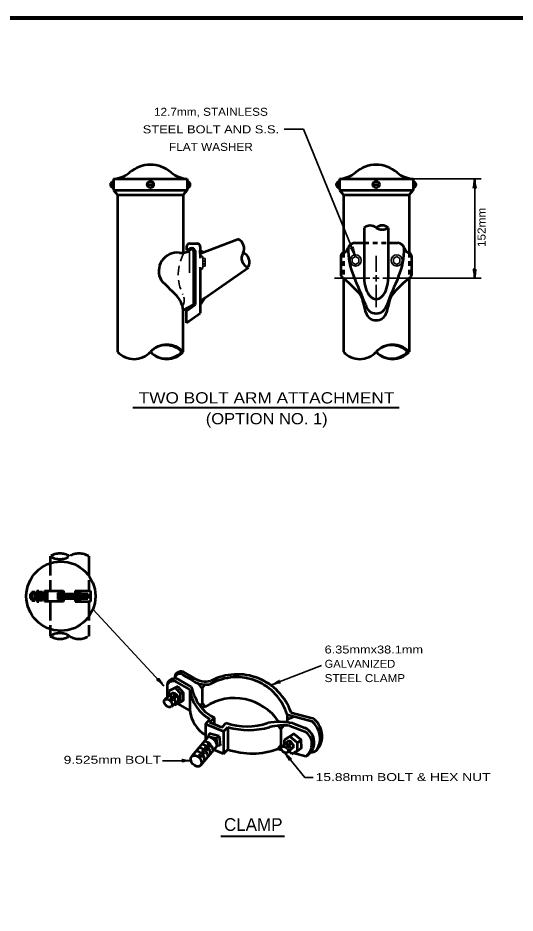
# Model space of a CAD drawing. Extents: x 6460 to 7173, y 270 to 723.
# Drawn here: x 6645 to 6801.5, y 436 to 717.8 of the extents above; entities that cross this region are included whole.
import ezdxf
from ezdxf.enums import TextEntityAlignment as Align

# ---------------------------------------------------------------- set-up
doc = ezdxf.new("R2010")
doc.units = 0
for name, pattern in [('LONG_DASHED', [7.5, 6, -1.5]), ('MEDIUM_DASHED', [4.5, 3, -1.5]), ('SHORT_DASHED', [2.7, 1.5, -1.2])]:
    doc.linetypes.add(name, pattern=pattern)
doc.layers.add('1', color=7, linetype='Continuous', lineweight=35)

msp = doc.modelspace()

# ---------------------------------------------------------------- linework, layer by layer
at = {"layer": '1'}
for p, q in [((6728.799, 682.801), (6734.872, 682.801)), ((6751.122, 642.92), (6734.872, 682.801)), ((6769.322, 667.1), (6790.742, 667.1)), ((6788.742, 667.1), (6788.742, 635.86)), ((6698.982, 637.52), (6698.982, 644.38)), ((6700.122, 627.44), (6700.122, 644.06)), ((6751.242, 642.68), (6750.222, 642.06)), ((6751.242, 642.68), (6752.242, 642.06)), ((6757.742, 642.92), (6757.742, 637.86)), ((6764.222, 642.68), (6763.222, 642.06)), ((6764.222, 642.68), (6765.222, 642.06)), ((6703.122, 639.08), (6703.122, 642.44)), ((6703.882, 641.26), (6703.142, 641.26)), ((6703.882, 640.4), (6703.142, 640.4)), ((6750.222, 642.06), (6750.222, 640.8)), ((6752.242, 642.06), (6752.242, 640.8)), ((6763.222, 642.06), (6763.222, 640.8)), ((6765.222, 642.06), (6765.222, 640.8)), ((6703.882, 639.66), (6703.142, 639.66)), ((6744.642, 635.86), (6755.742, 635.86)), ((6756.702, 635.86), (6758.722, 635.86)), ((6757.742, 636.84), (6757.742, 634.84)), ((6759.782, 635.86), (6790.742, 635.86)), ((6757.742, 633.82), (6757.742, 626.78)), ((6668.533, 531.678), (6690.869, 507.577)), ((6724.751, 507.828), (6740.562, 513.979)), ((6699.435, 483.978), (6690.434, 483.978))]:
    msp.add_line(p, q, dxfattribs=at)
at = {"layer": '1', "lineweight": 53}
for p, q in [((6674.082, 665.34), (6674.822, 665.34)), ((6675.082, 667.1), (6698.262, 667.1)), ((6675.082, 667.1), (6675.082, 663.58)), ((6685.902, 665.34), (6687.422, 665.34)), ((6698.262, 667.1), (6698.262, 663.58)), ((6698.522, 665.34), (6699.222, 665.34)), ((6745.142, 665.34), (6745.902, 665.34)), ((6746.142, 667.1), (6769.322, 667.1)), ((6746.142, 667.1), (6746.142, 663.58)), ((6756.982, 665.34), (6758.482, 665.34)), ((6769.322, 667.1), (6769.322, 663.58)), ((6769.582, 665.34), (6770.282, 665.34)), ((6675.082, 663.58), (6698.262, 663.58)), ((6675.082, 663.58), (6676.342, 662.06)), ((6698.262, 663.58), (6697.002, 662.06)), ((6746.142, 663.58), (6769.322, 663.58)), ((6746.142, 663.58), (6747.402, 662.06)), ((6769.322, 663.58), (6768.062, 662.06)), ((6676.342, 662.06), (6676.342, 612.68)), ((6676.342, 662.06), (6697.002, 662.06)), ((6697.002, 662.06), (6697.002, 643.92)), ((6747.402, 662.06), (6768.062, 662.06)), ((6747.402, 662.06), (6747.402, 643.92)), ((6768.062, 662.06), (6768.062, 643.92)), ((6753.962, 651.74), (6753.962, 635.86)), ((6761.522, 651.74), (6761.522, 635.86)), ((6702.362, 643.64), (6714.222, 648.18)), ((6698.022, 645.76), (6698.022, 644.72)), ((6699.022, 646.76), (6701.362, 646.76)), ((6702.362, 645.76), (6702.362, 645.24)), ((6750.882, 646.98), (6753.962, 646.98)), ((6761.522, 646.98), (6764.582, 646.98)), ((6698.022, 644.72), (6698.522, 644.72)), ((6700.902, 627.58), (6700.902, 643.76)), ((6702.362, 645.24), (6702.362, 642.2)), ((6746.642, 642.92), (6746.642, 636.86)), ((6768.822, 642.92), (6768.822, 636.86)), ((6702.362, 639.32), (6702.362, 629.74)), ((6702.362, 628.68), (6717.502, 639.28)), ((6747.402, 635.86), (6747.402, 612.68)), ((6768.062, 635.86), (6768.062, 612.68)), ((6702.362, 629.74), (6702.362, 624.9)), ((6697.002, 625.78), (6700.122, 627.44)), ((6697.002, 612.68), (6697.002, 625.78)), ((6698.022, 625.56), (6700.902, 627.58)), ((6698.022, 621.86), (6698.022, 625.56)), ((6698.022, 621.86), (6702.362, 624.9)), ((6648.782, 536.53), (6648.782, 535.01)), ((6648.782, 536.53), (6653.322, 536.53)), ((6649.082, 535.91), (6649.082, 535.61)), ((6649.382, 537.13), (6649.382, 534.41)), ((6649.382, 537.13), (6650.302, 537.13)), ((6650.302, 537.13), (6650.302, 534.41)), ((6650.902, 537.43), (6650.902, 534.11)), ((6650.902, 537.43), (6651.502, 537.43)), ((6651.502, 537.43), (6651.502, 534.11)), ((6652.122, 537.13), (6652.122, 534.41)), ((6652.122, 537.13), (6652.722, 537.13)), ((6652.722, 537.13), (6652.722, 534.41)), ((6653.322, 537.43), (6653.322, 534.11)), ((6653.322, 537.43), (6659.362, 537.43)), ((6654.222, 537.43), (6654.222, 534.11)), ((6657.562, 536.83), (6658.762, 536.83)), ((6657.562, 536.83), (6657.562, 534.71)), ((6657.862, 536.23), (6658.762, 536.23)), ((6658.762, 537.43), (6658.762, 534.11)), ((6659.362, 537.43), (6659.362, 534.11)), ((6659.822, 536.07), (6659.822, 535.47)), ((6660.282, 536.53), (6660.282, 535.01)), ((6660.722, 536.07), (6660.722, 535.47)), ((6661.182, 536.53), (6661.182, 535.01)), ((6661.642, 536.07), (6661.642, 535.47)), ((6662.102, 536.53), (6662.102, 535.01)), ((6662.542, 536.07), (6662.542, 535.47)), ((6663.002, 537.43), (6663.002, 534.11)), ((6663.002, 537.43), (6667.842, 537.43)), ((6663.602, 537.43), (6663.602, 534.11)), ((6664.822, 536.83), (6663.622, 536.83)), ((6664.522, 536.23), (6663.622, 536.23)), ((6664.822, 535.61), (6664.522, 535.31)), ((6664.822, 536.83), (6664.822, 534.71)), ((6665.342, 536.07), (6665.342, 535.47)), ((6665.882, 536.53), (6665.882, 535.01)), ((6666.402, 536.07), (6666.402, 535.47)), ((6666.922, 536.53), (6666.922, 535.01)), ((6667.842, 537.43), (6667.842, 534.11)), ((6648.782, 535.01), (6653.322, 535.01)), ((6649.382, 534.41), (6650.302, 534.41)), ((6650.902, 534.11), (6651.502, 534.11)), ((6652.722, 534.41), (6652.122, 534.41)), ((6659.362, 534.11), (6653.322, 534.11)), ((6657.562, 534.71), (6658.762, 534.71)), ((6657.862, 535.31), (6658.762, 535.31)), ((6663.002, 534.11), (6667.842, 534.11)), ((6664.522, 535.31), (6663.622, 535.31)), ((6664.822, 534.71), (6663.622, 534.71)), ((6664.522, 535.31), (6664.822, 535.01)), ((6700.179, 510.074), (6696.959, 511.914)), ((6700.179, 509.114), (6696.959, 510.934)), ((6691.919, 507.834), (6691.919, 503.814)), ((6695.259, 507.354), (6692.579, 505.934)), ((6699.039, 506.354), (6695.019, 508.654)), ((6699.539, 507.234), (6695.519, 509.514)), ((6702.979, 506.694), (6701.699, 508.334)), ((6702.979, 506.694), (6703.939, 507.934)), ((6693.479, 505.234), (6691.219, 503.194)), ((6692.579, 504.434), (6692.579, 505.934)), ((6694.499, 506.954), (6696.119, 505.154)), ((6699.039, 506.354), (6699.039, 499.794)), ((6695.499, 502.974), (6693.259, 500.954)), ((6694.099, 501.734), (6694.299, 501.494)), ((6699.039, 499.794), (6695.239, 501.954)), ((6702.979, 502.154), (6703.919, 500.974)), ((6702.499, 501.154), (6703.919, 500.974)), ((6730.919, 499.174), (6737.739, 497.354)), ((6704.059, 495.514), (6705.419, 497.014)), ((6705.379, 496.054), (6706.739, 497.554)), ((6709.099, 494.474), (6705.379, 496.054)), ((6706.739, 497.554), (6706.739, 495.474)), ((6729.699, 498.474), (6737.479, 496.374)), ((6729.699, 498.474), (6729.699, 496.054)), ((6729.819, 497.014), (6731.899, 497.874)), ((6709.639, 493.154), (6704.059, 495.514)), ((6704.059, 495.514), (6704.059, 490.534)), ((6709.099, 494.474), (6710.519, 495.894)), ((6709.639, 493.154), (6711.059, 494.574)), ((6709.639, 493.154), (6709.639, 486.094)), ((6711.059, 494.574), (6711.059, 487.514)), ((6727.739, 493.954), (6726.899, 495.014)), ((6727.739, 493.954), (6728.619, 495.094)), ((6727.739, 493.954), (6727.739, 488.914)), ((6730.579, 494.994), (6735.299, 493.194)), ((6731.459, 495.774), (6735.239, 494.334)), ((6704.899, 491.534), (6699.719, 485.354)), ((6705.139, 492.514), (6704.899, 491.534)), ((6707.399, 490.914), (6704.899, 491.534)), ((6708.319, 491.734), (6705.139, 492.514)), ((6708.319, 491.734), (6707.399, 490.914)), ((6707.399, 490.914), (6707.659, 488.614)), ((6708.319, 491.734), (6708.659, 488.734)), ((6728.919, 489.174), (6728.879, 490.534)), ((6732.919, 489.654), (6730.599, 491.594)), ((6707.659, 488.614), (6702.459, 482.434)), ((6708.659, 488.734), (6707.659, 488.614)), ((6709.639, 486.094), (6711.059, 487.514)), ((6727.739, 488.914), (6726.799, 487.714)), ((6726.799, 487.714), (6727.899, 487.414)), ((6727.739, 488.914), (6728.119, 488.414)), ((6730.099, 490.274), (6727.879, 488.214)), ((6731.819, 488.434), (6729.979, 486.714)), ((6709.639, 486.094), (6706.619, 487.374)), ((6731.219, 486.174), (6730.259, 486.974)), ((6731.679, 486.414), (6735.559, 485.374))]:
    msp.add_line(p, q, dxfattribs=at)
at = {"layer": '1', "linetype": 'SHORT_DASHED', "lineweight": 53}
for p, q in [((6753.962, 646.98), (6761.522, 646.98)), ((6747.402, 643.92), (6747.402, 635.86)), ((6768.062, 643.92), (6768.062, 635.86))]:
    msp.add_line(p, q, dxfattribs=at)
at = {"layer": '1', "lineweight": 40}
for p, q in [((6681.102, 595.14), (6764.982, 595.14)), ((6708.814, 460.253), (6728.892, 460.253))]:
    msp.add_line(p, q, dxfattribs=at)
at = {"layer": '1', "linetype": 'LONG_DASHED', "lineweight": 53}
for p, q in [((6655.142, 548.31), (6655.142, 537.43)), ((6667.242, 548.31), (6667.242, 537.43)), ((6655.142, 534.11), (6655.142, 523.21)), ((6667.242, 534.11), (6667.242, 523.21))]:
    msp.add_line(p, q, dxfattribs=at)
at = {"layer": '1', "lineweight": 158}
msp.add_lwpolyline([(7167.871, 717.799), (6508.121, 717.715), (6508.204, 279.382)], dxfattribs=at)
at = {"layer": '1', "lineweight": 53}
for points in [[(6703.462, 644.06), (6702.362, 643.64), (6702.362, 644.68)], [(6702.382, 627.44), (6702.382, 628.7), (6704.042, 629.88)], [(6657.562, 536.53), (6657.862, 536.23), (6657.562, 535.91)], [(6657.562, 535.61), (6657.862, 535.31), (6657.562, 535.01)], [(6659.362, 536.53), (6660.282, 536.53), (6661.182, 536.53), (6662.102, 536.53), (6663.002, 536.53)], [(6664.822, 536.53), (6664.522, 536.23), (6664.822, 535.91)], [(6664.822, 536.53), (6665.882, 536.53), (6666.922, 536.53)], [(6659.362, 535.01), (6661.182, 535.01), (6663.002, 535.01)], [(6664.822, 535.01), (6665.882, 535.01), (6666.922, 535.01)], [(6695.259, 507.354), (6696.939, 505.494), (6696.939, 502.974), (6696.119, 502.394), (6694.299, 501.494)], [(6696.119, 502.394), (6696.119, 505.154), (6696.939, 505.494)], [(6702.979, 506.694), (6702.979, 502.154), (6702.339, 501.354)], [(6731.219, 486.174), (6732.999, 487.134), (6734.239, 487.994), (6734.159, 490.514), (6731.839, 492.454), (6728.879, 490.534)], [(6732.999, 487.134), (6732.919, 489.654), (6734.159, 490.514)]]:
    msp.add_lwpolyline(points, dxfattribs=at)
at = {"layer": '1'}
for points in [[(6703.882, 639.66), (6703.882, 642.02), (6703.142, 642.02)], [(6752.242, 640.8), (6751.242, 640.16), (6750.222, 640.8)], [(6765.222, 640.8), (6764.222, 640.16), (6763.222, 640.8)], [(6728.898, 486.568), (6735.292, 478.706), (6737.927, 478.706)]]:
    msp.add_lwpolyline(points, dxfattribs=at)
at = {"layer": '1', "lineweight": 53}
for centre, radius in [((6686.667, 665.34), 1.008), ((6757.731, 665.34), 1.008), ((6658.497, 535.774), 10.886)]:
    msp.add_circle(centre, radius, dxfattribs=at)
at = {"layer": '1'}
for centre in [(6751.248, 641.454), (6764.227, 641.446)]:
    msp.add_circle(centre, 1.764, dxfattribs=at)
at = {"layer": '1', "lineweight": 53}
for centre, radius, start, end in [((6686.673, 661.531), 10.025, 49.18722, 130.81278), ((6757.737, 661.531), 10.025, 49.18722, 130.81278), ((6674.151, 676.735), 9.678, 275.5142, 308.08862), ((6699.195, 676.735), 9.678, 231.91138, 264.4858), ((6745.215, 676.735), 9.678, 275.5142, 308.08862), ((6770.259, 676.735), 9.678, 231.91138, 264.4858), ((6675.087, 665.312), 1.008, 90.3199, 269.6801), ((6698.218, 665.312), 1.008, 272.67956, 87.32044), ((6746.151, 665.312), 1.008, 90.3199, 269.6801), ((6769.282, 665.312), 1.008, 272.67956, 87.32044), ((6755.847, 649.542), 2.891, 49.17959, 130.82041), ((6759.627, 649.649), 2.812, 47.76241, 132.23758), ((6759.627, 654.476), 3.333, 235.45601, 304.54399), ((6712.915, 645.177), 3.282, 333.96531, 66.42353), ((6699.021, 645.755), 1.008, 90, 180), ((6701.356, 645.755), 1.008, 0, 90), ((6746.746, 645.959), 2.235, 294.0674, 346.32146), ((6771.756, 645.164), 22.84, 179.33091, 202.67617), ((6751.02, 644.782), 2.2, 93.41837, 162.8601), ((6764.455, 644.782), 2.2, 17.1399, 86.58162), ((6743.719, 645.164), 22.84, 337.32383, 0.66909), ((6768.729, 645.959), 2.235, 193.67854, 245.9326), ((6695.102, 638.114), 5.805, 83.22236, 210.1126), ((6696.073, 652.427), 8.553, 268.07998, 289.90391), ((6699.611, 643.99), 1.312, 350.09958, 146.42495), ((6703.777, 645.898), 1.866, 221.01419, 260.32206), ((6718.267, 642.095), 2.91, 145.65086, 254.73799), ((6714.611, 640.856), 3.282, 333.96531, 66.42353), ((6747.714, 642.853), 1.067, 93.07015, 176.92984), ((6767.76, 642.853), 1.067, 3.07016, 86.92985), ((6747.714, 636.919), 1.067, 183.07016, 253.15341), ((6767.76, 636.919), 1.067, 286.84659, 356.92984), ((7805.326, 1750.591), 1577.297, 225.00367, 225.22952), ((6720.251, 603.149), 42.543, 42.29957, 50.33685), ((6568.182, 554.45), 200.037, 21.39177, 24.17121), ((6951.517, 552.676), 204.618, 155.85991, 158.57712), ((6795.223, 603.149), 42.543, 129.66315, 138.49633), ((6748.598, 627.807), 5.052, 9.48157, 51.86654), ((6767.078, 627.474), 5.329, 133.87214, 169.50589), ((6688.926, 624.885), 8.128, 6.28285, 46.84726), ((6710.958, 623.346), 9.51, 136.62273, 154.46868), ((6675.522, 606.627), 81.104, 13.13509, 15.74771), ((6839.953, 606.627), 81.104, 163.98892, 166.86491), ((6757.737, 628.174), 3.386, 193.00171, 346.99829), ((6757.737, 625.968), 3.36, 195.72161, 344.27839), ((6691.839, 607.854), 7.063, 42.99091, 137.00909), ((6691.579, 607.981), 6.786, 43.44505, 136.28697), ((6762.903, 607.854), 7.063, 42.99091, 137.00909), ((6762.643, 607.981), 6.786, 43.44505, 136.28697), ((6681.507, 617.486), 7.063, 222.99091, 317.00909), ((6691.839, 617.486), 7.063, 222.99091, 317.00909), ((6691.6, 617.326), 6.779, 223.38031, 316.35171), ((6752.571, 617.486), 7.063, 222.99091, 317.00909), ((6762.903, 617.486), 7.063, 222.99091, 317.00909), ((6762.664, 617.326), 6.779, 223.38031, 316.35171), ((6696.262, 510.077), 1.967, 68.98454, 184.96528), ((6695.905, 509.73), 1.613, 48.79801, 173.73367), ((6704.074, 516.05), 7.131, 236.83956, 283.32479), ((6714.037, 493.271), 17.892, 19.29143, 117.70819), ((6713.827, 493.697), 16.566, 16.7434, 119.30902), ((6694.333, 507.361), 2.464, 61.16852, 169.07366), ((6693.826, 506.869), 2.14, 56.06469, 153.37669), ((6704.022, 514.783), 6.854, 235.84201, 284.32234), ((6693.62, 503.323), 1.909, 349.61263, 94.38617), ((6693.244, 502.994), 1.742, 20.88408, 69.09679), ((6711.687, 508.143), 12.777, 188.06983, 240.59731), ((6720.612, 512.954), 21.84, 195.21089, 204.37149), ((6692.648, 502.453), 1.909, 349.61263, 94.38617), ((6692.192, 502.067), 1.742, 20.88408, 69.09679), ((6711.867, 508.402), 12.008, 201.80286, 244.70416), ((6713.072, 486.783), 16.89, 33.86522, 122.8499), ((6709.752, 501.171), 10.803, 187.30417, 238.23787), ((6727.212, 474.447), 21.748, 78.72641, 99.48511), ((6733.153, 490.957), 6.939, 327.83586, 51.43283), ((6733.979, 491.748), 6.752, 318.38164, 56.15447), ((6717.076, 514.154), 19.396, 250.25742, 289.74258), ((6717.61, 516.375), 22.763, 253.27137, 286.72862), ((6728.644, 475.321), 19.77, 84.35687, 103.10294), ((6733.254, 489.771), 4.969, 297.71146, 66.56345), ((6732.821, 489.19), 4.701, 305.70046, 58.26699), ((6704.468, 488.36), 3.193, 4.65558, 82.27962), ((6701.658, 484.847), 3.193, 7.29827, 83.92311), ((6702.422, 485.916), 3.193, 4.74535, 82.35434), ((6703.108, 486.603), 1.531, 14.18506, 70.66849), ((6703.247, 486.924), 3.193, 4.32722, 81.54855), ((6703.902, 487.673), 1.531, 14.18506, 70.66849), ((6718.651, 509.525), 23.278, 250.96338, 290.4942), ((6728.592, 487.125), 2.406, 11.41742, 74.57891), ((6728.836, 487.435), 1.432, 21.50211, 64.13038), ((6729.458, 487.95), 2.406, 11.41742, 74.57891), ((6729.712, 488.237), 1.432, 21.50211, 64.13038), ((6700.651, 483.778), 3.193, 5.19441, 82.73082), ((6701.275, 484.465), 1.531, 14.18506, 70.66849), ((6702.252, 485.565), 1.531, 14.18506, 70.66849), ((6736.852, 490.31), 3.743, 273.11257, 305.52158)]:
    msp.add_arc(centre, radius, start, end, dxfattribs=at)
at = {"layer": '1', "linetype": 'MEDIUM_DASHED'}
for centre, radius, start, end in [((6709.666, 636.948), 14.228, 150.47291, 206.06704), ((6693.269, 628.929), 4.026, 330.81735, 26.04877)]:
    msp.add_arc(centre, radius, start, end, dxfattribs=at)
at = {"layer": '1'}
for centre, radius, start, end in [((6699.538, 644.172), 0.593, 349.37883, 158.91973), ((6702.406, 642.274), 0.738, 13.64106, 87.59419), ((6702.406, 639.246), 0.738, 272.40581, 346.35894)]:
    msp.add_arc(centre, radius, start, end, dxfattribs=at)
at = {"layer": '1', "linetype": 'LONG_DASHED', "lineweight": 53}
for centre, start, end in [((6658.162, 543.585), 57.42639, 122.57361), ((6658.162, 553.052), 237.42639, 302.57361), ((6664.21, 543.585), 57.42639, 122.57361), ((6658.162, 518.486), 57.42639, 122.57361), ((6658.162, 527.953), 237.42639, 302.57361), ((6664.21, 527.953), 237.42639, 302.57361)]:
    msp.add_arc(centre, 5.617, start, end, dxfattribs=at)
at = {"layer": '1', "lineweight": 40}
for centre, major_axis, ratio, start_param, end_param in [((6788.52, 665.973), (0.177, 1.77), 0.07063, 3.1407148, 5.41811), ((6789.012, 666.002), (-0.157, 1.8), 0.122415, 0.8963533, 3.1415927), ((6750.444, 643.832), (0.824, -1.608), 0.122415, 0.8963533, 3.1415927), ((6750.888, 644.045), (-0.503, 1.707), 0.07063, 6.2823074, 8.5597026), ((6788.455, 636.954), (0.157, -1.8), 0.122415, 0.8963533, 3.1415927), ((6788.947, 636.984), (-0.177, -1.77), 0.07063, 3.1407148, 5.41811), ((6689.925, 508.19), (1.328, -1.204), 0.122415, 0.8963533, 3.1415927), ((6690.263, 508.543), (1.065, -1.408), 0.07063, 3.1407148, 5.41811), ((6725.668, 508.481), (-1.608, -0.793), 0.122415, 0.8963533, 3.1415927), ((6725.668, 508.481), (-1.608, -0.793), 0.122415, 0.8963533, 3.1415927), ((6725.872, 508.037), (-1.701, -0.473), 0.07063, 3.1407148, 5.41811), ((6725.872, 508.037), (-1.701, -0.473), 0.07063, 3.1407148, 5.41811), ((6729.44, 485.565), (0.972, -1.474), 0.07063, 6.2823074, 8.5597026), ((6729.44, 485.565), (0.972, -1.474), 0.07063, 6.2823074, 8.5597026), ((6729.801, 485.896), (-1.248, 1.287), 0.122415, 0.8963533, 3.1415927), ((6729.801, 485.896), (-1.248, 1.287), 0.122415, 0.8963533, 3.1415927), ((6698.344, 483.702), (1.786, 0.156), 0.122415, 0.8963533, 3.1415927), ((6698.344, 483.702), (1.786, 0.156), 0.122415, 0.8963533, 3.1415927), ((6698.314, 484.189), (1.756, -0.176), 0.07063, 3.1407148, 5.41811), ((6698.314, 484.189), (1.756, -0.176), 0.07063, 3.1407148, 5.41811)]:
    msp.add_ellipse(centre, major_axis=major_axis, ratio=ratio, start_param=start_param, end_param=end_param, dxfattribs=at)
at = {"layer": '1', "lineweight": 53}
msp.add_ellipse((6757.737, 635.854), major_axis=(0, 6.553), ratio=0.576878, start_param=1.5707963, end_param=4.712389, dxfattribs=at)
for centre, major_axis, ratio in [((6692.239, 502.079), (1.012, -1.124), 0.663346), ((6728.929, 487.458), (1.044, -0.75), 0.624582), ((6701.091, 483.895), (1.377, -1.452), 0.71432)]:
    msp.add_ellipse(centre, major_axis=major_axis, ratio=ratio, dxfattribs=at)

# ---------------------------------------------------------------- texts
at = {"layer": '1'}
for s, height, width, p in [('12.7mm, STAINLESS', 2.52, 1.1, (6705.712, 686.981)), ('STEEL BOLT AND S.S.', 2.52, 1.2, (6705.712, 681.461)), ('FLAT WASHER', 2.52, 1.1, (6705.712, 675.941)), ('TWO BOLT ARM ATTACHMENT', 3.528, 1.15, (6723.222, 596.44)), ('(OPTION NO. 1)', 3.528, 1.1, (6723.27, 589.88))]:
    msp.add_text(s, height=height, dxfattribs=dict(at, width=width)).set_placement(p, align=Align.CENTER)
at = {"layer": '1', "width": 1.1}
msp.add_text('152mm', height=2.52, rotation=90, dxfattribs=at).set_placement((6792.161, 645.672))
at = {"layer": '1'}
for s, width, p in [('6.35mmx38.1mm', 1.2, (6741.499, 517.725)), ('GALVANIZED', 1.05, (6741.499, 513.225)), ('STEEL CLAMP', 1.1, (6741.499, 508.725)), ('9.525mm BOLT', 1.3, (6659.368, 483.019)), ('15.88mm BOLT & HEX NUT', 1.3, (6738.68, 477.576))]:
    msp.add_text(s, height=2.5, dxfattribs=dict(at, width=width)).set_placement(p)
msp.add_text('CLAMP', height=4, dxfattribs=at).set_placement((6709.818, 461.885))

doc.saveas('drawing.dxf')
